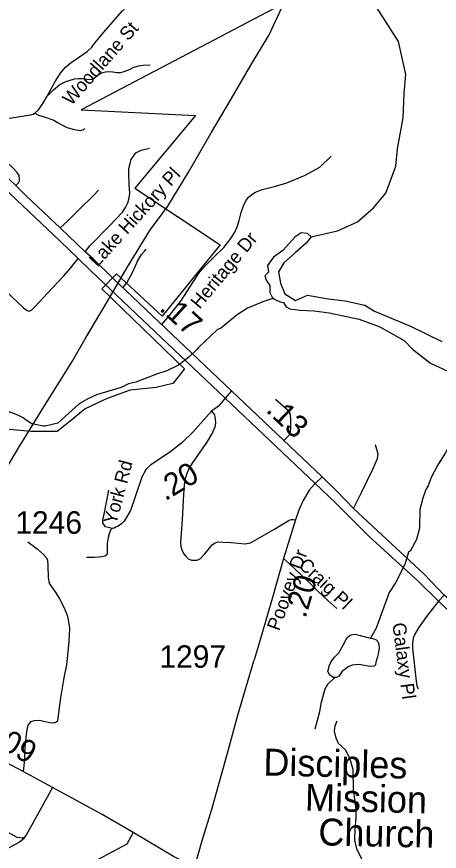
# Model space of a CAD drawing. Extents: x 1159738 to 1321356, y 736314 to 882035.
# Drawn here: x 1283208 to 1285565, y 749048 to 753698 of the extents above; entities that cross this region are included whole.
import ezdxf

# ---------------------------------------------------------------- set-up
doc = ezdxf.new("R2010")
doc.units = 0
for name, color, linetype in [('Exist Boundary Political City Limit New', 7, 'Continuous'), ('Exist Cultural Church Label', 7, 'Continuous'), ('Exist Hydrographic Creek Double Shore', 7, 'Continuous'), ('Exist Hydrographic Creek Single Shore', 7, 'Continuous'), ('Exist Hydrographic Misc Water Feature', 7, 'Continuous'), ('Exist Road Non-System Type 51', 7, 'Continuous'), ('Exist Road Non-System Type 51 Label', 7, 'Continuous'), ('Exist Road Primary US Attributed', 7, 'Continuous'), ('Exist Road Primary US Divided Attributed', 7, 'Continuous'), ('Exist Road Primary US Mileage Hundredths English Label', 7, 'Continuous'), ('Exist Road Secondary Mileage Hundredths English Label', 7, 'Continuous'), ('Exist Road Secondary Type 51 Attributed', 7, 'Continuous'), ('Exist Road Secondary Type 51 Label', 7, 'Continuous'), ('Exist Road Secondary Type 51 Number Label', 7, 'Continuous'), ('Exist Utilities Electrical Transmission Line', 7, 'Continuous'), ('Map Preparation Boundary City Limit Buffer Line', 7, 'Continuous')]:
    doc.layers.add(name, color=color, linetype=linetype)

msp = doc.modelspace()

# ---------------------------------------------------------------- linework, layer by layer
at = {"layer": 'Exist Boundary Political City Limit New'}
msp.add_lwpolyline([(1285086.5, 753976.7), (1283568.2, 753178.6), (1284205.4, 753147.8), (1283867.6, 752743), (1284343.3, 752426.5), (1284218.6, 752275.2), (1284019, 752029.4), (1283765.6, 752265.6), (1283683.1, 752181.1), (1284143.7, 751735.5), (1284078.5, 751654.9), (1283986.4, 751631.8), (1283840.5, 751616.5), (1283713.8, 751570.4), (1283591, 751512.8), (1283506.5, 751443.6), (1283433.9, 751386.4), (1283288.1, 751386.4), (1283007.9, 751413.3)], dxfattribs=at)
at = {"layer": 'Exist Hydrographic Creek Double Shore'}
for points in [[(1284849.9, 752471.5), (1284829.7, 752489.5), (1284795.7, 752493.1), (1284760.7, 752470.7), (1284727.6, 752434.9), (1284691.8, 752395.5), (1284639.9, 752357.8), (1284606.8, 752311.2), (1284613, 752274.5), (1284592.4, 752254.8), (1284599.6, 752230.6), (1284621.1, 752200.1), (1284620.2, 752160.7), (1284637.2, 752128.5), (1284677.5, 752108.8), (1284696.3, 752105.2), (1284711.4, 752080.6), (1284731.1, 752069.9), (1284787.5, 752062.7), (1284868.1, 752059.1), (1284950.4, 752048.3), (1285118.8, 752013.4), (1285234.2, 751970.4), (1285368.5, 751893.4), (1285416.4, 751845.4), (1285516.7, 751767.4), (1285693, 751685)], [(1284849.9, 752471.5), (1284822.5, 752436.2), (1284761.5, 752383.1), (1284697.8, 752327.3), (1284668.6, 752276.8), (1284679.2, 752213.1), (1284703.1, 752154.6), (1284764.1, 752117.4), (1284830.5, 752146.6), (1284944.7, 752125.4), (1285040.2, 752114.8), (1285149.1, 752090.8), (1285204.8, 752056.3), (1285403.9, 751974), (1285579.1, 751888.9)]]:
    msp.add_lwpolyline(points, dxfattribs=at)
at = {"layer": 'Exist Hydrographic Creek Single Shore'}
msp.add_lwpolyline([(1284849.9, 752471.5), (1284997.7, 752504.4), (1285108.6, 752555.7), (1285198.9, 752633.8), (1285266.6, 752713.9), (1285322.8, 752865.6), (1285332.3, 752962.4), (1285363.1, 753135), (1285369.3, 753272.6), (1285379, 753376.3), (1285336.8, 753559), (1285282.7, 753647), (1285218.8, 753745.6), (1285174, 753868.3)], dxfattribs=at)
at = {"layer": 'Exist Hydrographic Misc Water Feature'}
for points in [[(1284643.1, 752129.4), (1284580.8, 752109.2), (1284496.5, 752073.3), (1284437.4, 752037.3), (1284344.5, 751960), (1284328.3, 751954.4), (1284221.6, 751855.5), (1284215.4, 751845.7), (1284168.1, 751801.1), (1284110.9, 751756.7), (1284045.9, 751724.6), (1283989, 751706.9), (1283872.1, 751661.6), (1283831.9, 751652.7), (1283791.3, 751631.9), (1283654.1, 751591.9), (1283605.5, 751569.3), (1283556.7, 751540.6), (1283437.7, 751434.1), (1283367.5, 751416.6), (1283357.2, 751416.4), (1283293.5, 751430.2), (1283262.1, 751449.1), (1283244.5, 751463.6), (1283214.9, 751478.5), (1283151.6, 751502.2)], [(1285940.2, 751598.4), (1285871.8, 751488.3), (1285831.4, 751473.4), (1285750.3, 751433.8), (1285684.9, 751383.7), (1285656.1, 751354.5), (1285629.1, 751321.3), (1285598.5, 751266.7), (1285555.7, 751197.4), (1285517.6, 751126.5), (1285502.5, 751085), (1285490, 751063.3), (1285472.6, 751015.8), (1285456.8, 750952.3), (1285454, 750848.4), (1285438.2, 750784.9), (1285403.5, 750721), (1285394.2, 750714.1), (1285372.4, 750646.8), (1285321.5, 750544.3), (1285285.9, 750489.3), (1285212.4, 750291.5), (1285181.8, 750236.2)], [(1284982.7, 750016.3), (1284973.4, 750017), (1284953.2, 750030.5), (1284944.2, 750052.6), (1284948.6, 750067.6), (1284951.1, 750080.5), (1284960.4, 750100.9), (1284980.4, 750130.5), (1285004.2, 750153.9), (1285030.8, 750200.5), (1285050.8, 750239.7), (1285062, 750248.3), (1285073.2, 750254.9), (1285095.9, 750257.7), (1285123.7, 750250.2), (1285166.7, 750239.5), (1285181.8, 750236.2)], [(1285181.8, 750236.2), (1285195.3, 750233.3), (1285213.7, 750226), (1285221.7, 750216.8), (1285228.1, 750202.3), (1285230.4, 750181.7), (1285225.7, 750157.2), (1285220.9, 750131.2), (1285211.3, 750102.7), (1285209.6, 750087.7), (1285202.5, 750079.6), (1285179.2, 750078.2), (1285146.4, 750083.8), (1285119.1, 750088.6), (1285097.2, 750087.8), (1285079.3, 750084.8), (1285061.3, 750077), (1285041.8, 750065.2), (1285022.1, 750047.2), (1285004.5, 750024.4), (1284991.9, 750015.8), (1284982.7, 750016.3)], [(1284982.7, 750016.3), (1284941.7, 749977.3), (1284927, 749951.7), (1284904.7, 749872.4), (1284897.5, 749824.6), (1284870.8, 749729.4)]]:
    msp.add_lwpolyline(points, dxfattribs=at)
at = {"layer": 'Exist Road Non-System Type 51'}
for points in [[(1283309, 753159.6), (1283331.5, 753180.2), (1283354.8, 753214.5), (1283378.8, 753255.7), (1283423.4, 753337.6), (1283453.6, 753382.3), (1283479.6, 753414.5), (1283514.6, 753444), (1283540, 753460.5), (1283600.9, 753503.6), (1283627.7, 753528.3), (1283648.9, 753555), (1283705.2, 753623.7), (1283798.3, 753729.6), (1283853.1, 753790.7), (1283868.2, 753814.7), (1283879.2, 753838.7), (1283884, 753849)], [(1283378.8, 753255.7), (1283414.3, 753291), (1283448.6, 753320.5), (1283478.1, 753334.9), (1283501.4, 753343.1), (1283530.2, 753350.7), (1283550.8, 753353.4), (1283573.4, 753354.1), (1283591.2, 753350.7), (1283609.1, 753347.9), (1283628.9, 753349.3), (1283647.5, 753361.7), (1283663.2, 753374.7), (1283681.1, 753385.7), (1283703, 753391.2), (1283722.9, 753391.8), (1283745.5, 753390.5), (1283766.1, 753386.4), (1283788.1, 753387.7), (1283807.9, 753391.8), (1283836.7, 753403.5), (1283857.3, 753413.8), (1283887.5, 753424.8), (1283912.9, 753428.2), (1283953.3, 753429.6)], [(1283203.3, 752756.5), (1283218, 752772.9), (1283223.5, 752783.9), (1283224.8, 752795.6), (1283222.1, 752813.4), (1283210.4, 752829.2), (1283184.4, 752858), (1283161.7, 752880), (1283148, 752900.6), (1283134.3, 752923.2), (1283124.7, 752948.6), (1283111, 753005.6), (1283098, 753088.9), (1283097.3, 753097.8), (1283100.8, 753109.5), (1283115.2, 753119.8), (1283143.3, 753130.1), (1283181, 753134.2), (1283252.3, 753144.5), (1283288, 753151.3), (1283300, 753155.5), (1283309, 753159.6)], [(1283309, 753159.6), (1283330.2, 753150), (1283362.5, 753140.4), (1283415.3, 753120.5), (1283436.5, 753108.1), (1283488, 753081.3), (1283531.2, 753069.7), (1283564.1, 753064.2), (1283577.8, 753067.6), (1283590.8, 753075.2)], [(1283590.4, 752388.5), (1283615.8, 752422.1), (1283726.9, 752532.6), (1283798.2, 752609.5), (1283816.1, 752634.2), (1283828.4, 752661), (1283835.3, 752687.7), (1283838.6, 752714.2), (1283835.9, 752762.9), (1283833.1, 752821.9), (1283833.8, 752845.9), (1283835.9, 752859.7), (1283840.7, 752879.6), (1283847.5, 752901.5), (1283863.3, 752926.6), (1283872.9, 752939), (1283888, 752947.2), (1283903.1, 752954.1), (1283949.7, 752965.8)], [(1284018, 751982.9), (1284060.5, 752032.3), (1284127, 752118.1), (1284191.5, 752217), (1284229.9, 752276), (1284264.7, 752314.7), (1284309.3, 752359.3), (1284363.5, 752412.2), (1284403.3, 752462.3), (1284424.5, 752497.3), (1284438.8, 752527.8), (1284449.1, 752562.1), (1284460.8, 752607.4), (1284475.9, 752650), (1284487.5, 752673.3), (1284499.9, 752691.2), (1284519.1, 752707.6), (1284539.5, 752720.4), (1284577.2, 752734.1), (1284645.8, 752751.9), (1284715.8, 752771.9), (1284813.2, 752813.7), (1284898.9, 752859), (1284961.6, 752920.4)], [(1283450.2, 752521.5), (1283494.8, 752562.7), (1283554.5, 752621), (1283638.1, 752704.1), (1283664.2, 752731.5)], [(1282910.3, 752650.6), (1282902.1, 752630), (1282893.9, 752601.1), (1282892.5, 752573.7), (1282893.2, 752535.3), (1282900.7, 752485.8), (1282914.4, 752442.6), (1282933.5, 752408.8), (1282961, 752362.8), (1283002.1, 752312.7), (1283100.9, 752215.2), (1283181.8, 752137), (1283246.7, 752076.2), (1283266.6, 752060.5), (1283277.6, 752057.7), (1283291.3, 752063.2), (1283308.5, 752079), (1283381.8, 752159.3), (1283471.7, 752253.3), (1283507.9, 752296.3), (1283543.5, 752341.6), (1283551.7, 752350.5)], [(1283802.2, 752188.4), (1283822.1, 752215.9), (1283854.3, 752273.5), (1283877.7, 752327), (1283881.8, 752335.3), (1283905.1, 752372.3), (1283920.9, 752390.9), (1283929.8, 752401.9)], [(1284651.8, 751566.7), (1284727.2, 751499.5), (1284733.4, 751480.3), (1284735.4, 751456.3), (1284734.8, 751409.6), (1284732.7, 751385.6), (1284727.2, 751366.3), (1284719, 751356.7), (1284697.7, 751336.8)], [(1284295.7, 751499.5), (1284312.1, 751479.6), (1284316.2, 751458.3), (1284316.9, 751434.9), (1284312.8, 751410.2), (1284302.5, 751384.2), (1284268.9, 751327.9), (1284232.6, 751277.8), (1284186.7, 751211.2), (1284173, 751187.2), (1284156.5, 751153.5), (1284148.9, 751122.7), (1284142.1, 751087.7), (1284138, 751036.9), (1284130.4, 750895.5), (1284122.2, 750770.3), (1284124.3, 750746.3), (1284129.8, 750727.7), (1284138, 750707.8), (1284149.7, 750694.1), (1284164.7, 750677.6), (1284182.6, 750670.1), (1284214.1, 750670.1), (1284232.6, 750679), (1284257.3, 750705.8), (1284299.8, 750756.6), (1284315.6, 750766.9), (1284330.7, 750771.7), (1284358.8, 750771), (1284404.8, 750768.2), (1284482.3, 750760.7), (1284512.4, 750766.9), (1284641.7, 750841), (1284728.1, 750892.4), (1284740.4, 750895.9), (1284754.8, 750895.9), (1284763.8, 750895.2)], [(1285087.3, 750957.2), (1285131.5, 751046.5), (1285193.9, 751176.2), (1285219.9, 751236.6), (1285224.7, 751261.3), (1285210.3, 751313.1)], [(1283740.1, 750847.2), (1283718.1, 750851.4), (1283704.2, 750856.2), (1283695.6, 750867.5), (1283689.1, 750878.8), (1283688.6, 750893.3), (1283696.1, 750926.7), (1283722.4, 751059.2)], [(1283740.1, 750847.2), (1283731, 750837.5), (1283723.4, 750817.1), (1283718.6, 750796.1), (1283713.2, 750762.8), (1283713.2, 750707.4), (1283710, 750698.7), (1283699.3, 750692.2), (1283682.6, 750689), (1283641.8, 750685.3), (1283598.3, 750685.3)], [(1283271, 750773.1), (1283322.1, 750733.4), (1283355.4, 750704.3), (1283374.5, 750683), (1283380.2, 750670.2), (1283382.3, 750637.6), (1283383.7, 750573.8), (1283388, 750551.8), (1283392.2, 750537.6), (1283426.2, 750487.3), (1283446.7, 750454.3), (1283471.5, 750408.9), (1283489.2, 750363.5), (1283496.3, 750337.3), (1283503.4, 750291.9), (1283498.5, 750215.3), (1283485.7, 750086.6), (1283471.5, 750014.2)], [(1284696.3, 750680), (1284727.1, 750651.9), (1284832.7, 750553.1), (1284885.6, 750499.5), (1284944.5, 750446), (1284994.5, 750401.7)], [(1285560.4, 750441), (1285593.1, 750475.1)], [(1285560.4, 750441), (1285493.2, 750356.6), (1285448.6, 750293.4), (1285428.1, 750257.7), (1285419.1, 750235.8), (1285415, 750206.9), (1285415.7, 750179.5), (1285428.8, 750062.7), (1285435.7, 749996.1), (1285439.1, 749970.7), (1285448, 749953.1)], [(1284201.2, 748963.6), (1284242.9, 749108), (1284297.5, 749282.5), (1284384.9, 749594), (1284441.6, 749805.9), (1284533.3, 750114.8)], [(1283471.5, 750014.2), (1283452.2, 749902.2), (1283444.3, 749834.8), (1283436.6, 749773.1), (1283428.1, 749767.2), (1283415, 749762), (1283392.8, 749764.6), (1283334.6, 749776.4), (1283305.2, 749775.7), (1283286.2, 749768.5), (1283269.9, 749750.8), (1283264, 749716.2), (1283254.2, 749631.2), (1283250.3, 749542.8), (1283243.9, 749492.2)], [(1285160.8, 748714.9), (1285162.9, 748759.5), (1285171.4, 748866.5), (1285170.3, 748901.8), (1285158.6, 748943.6), (1285138.3, 748992.8), (1285105.1, 749062.3), (1285094.4, 749110), (1285096.6, 749172.1), (1285101.9, 749235.2), (1285100.8, 749284.5), (1285085.9, 749390.4), (1285084.8, 749503.1), (1285066.6, 749567.3), (1285042, 749613.3), (1285002.5, 749648.6), (1284989.6, 749677.5), (1284981.1, 749718.2), (1284985.4, 749747), (1284995, 749775.9)], [(1283858.9, 749153.3), (1283821.9, 749088.3), (1283771, 749060.6), (1283546.9, 748940.4)], [(1283249.8, 749125.8), (1283249.3, 749119), (1283224.4, 749099.8), (1283180.3, 749074.4), (1283139.9, 749052.5), (1283121.7, 749033.8)]]:
    msp.add_lwpolyline(points, dxfattribs=at)
at = {"layer": 'Exist Road Primary US Attributed'}
for points in [[(1283407.4, 749404.1), (1283306.3, 749458.5), (1283243.9, 749492.2), (1283073.5, 749582.2), (1282976.8, 749635.9)], [(1286675.2, 748116.7), (1286461.5, 748240.3), (1286275.2, 748348.8), (1286158, 748417), (1286032.3, 748489.6), (1285885, 748573.2), (1285741.8, 748641.3), (1285612.7, 748681.1), (1285461.2, 748705.6), (1285417.3, 748710.2), (1285160.8, 748714.9), (1284962.1, 748721.8), (1284717.2, 748738), (1284590.1, 748765.7), (1284498.9, 748808.8), (1284339.5, 748887.4), (1284189.3, 748966), (1284083, 749019.2), (1283858.9, 749153.3), (1283685.6, 749252.7), (1283497.3, 749354.4), (1283407.4, 749404.1)]]:
    msp.add_lwpolyline(points, dxfattribs=at)
at = {"layer": 'Exist Road Primary US Divided Attributed'}
msp.add_line((1284370.9, 751572.6), (1284872.9, 751097.8), dxfattribs=at)
for points in [[(1281205.3, 754875), (1281282.7, 754750.9), (1281327.3, 754673.8), (1281422.8, 754516.8), (1281495.9, 754411.3), (1281539, 754348.9), (1281607.8, 754256.1), (1281659.7, 754192.1), (1281733.9, 754102), (1281817.1, 754010.1), (1281889.7, 753933.7), (1281977.6, 753846.5), (1282175.6, 753654.8), (1282321.8, 753516.3), (1282602, 753249.9), (1282794.5, 753067.1), (1282993.2, 752875.7), (1283115.9, 752762.2), (1283169.4, 752712.1), (1283311, 752579.4), (1283449.2, 752449), (1283551.7, 752350.5), (1283622.4, 752282.2), (1284370.9, 751572.6)], [(1284406.3, 751613.3), (1283745.3, 752241.8), (1283636.2, 752347), (1283590.4, 752388.5), (1283450.2, 752521.5), (1283263.2, 752698.3), (1283203.3, 752756.5), (1282971, 752973.8), (1282755.9, 753180.7), (1282403.6, 753512.5), (1282105.3, 753798.8), (1281961.9, 753936.1), (1281907.4, 753991.9), (1281804.9, 754105.5), (1281722.9, 754199.3), (1281650.6, 754291.4)], [(1284912.1, 751134.3), (1284406.3, 751613.3)], [(1284872.9, 751097.8), (1284986.3, 750989.7), (1285174.8, 750801.2), (1285446.5, 750553.2), (1285560.4, 750441), (1285596.1, 750408.8), (1285753.3, 750258.2), (1285967, 750055.5), (1286666.3, 749398.8), (1287841.8, 748278.8), (1288179.5, 747958.8), (1288566, 747590.6), (1288742, 747424.7), (1288842.6, 747327.9), (1289075.6, 747102.7), (1289184.2, 746990.5), (1289284.9, 746874.5)], [(1289566.8, 746622.3), (1289339.6, 746898.3), (1289190.4, 747065.5), (1288874.1, 747374), (1288770.3, 747471.8), (1288618.2, 747616.8), (1288206.3, 748007), (1287893.4, 748301.5), (1287879.6, 748317.4), (1286883.7, 749263.7), (1286696.8, 749439.3), (1286597.1, 749535), (1286435.2, 749688.5), (1286334.8, 749781.3), (1285667, 750411.7), (1285593.1, 750475.1), (1285480.4, 750591.9), (1285087.3, 750957.2), (1284989.7, 751058.2), (1284912.1, 751134.3)]]:
    msp.add_lwpolyline(points, dxfattribs=at)
at = {"layer": 'Exist Road Secondary Type 51 Attributed'}
for points in [[(1284406.3, 751613.3), (1284370.9, 751572.6)], [(1284370.9, 751572.6), (1284333.8, 751528), (1284295.7, 751499.5), (1284191.4, 751383.4), (1284129.3, 751323.9), (1284068, 751275), (1283955.3, 751199.9), (1283930.1, 751176.2), (1283907, 751133.3), (1283871.1, 751027.7), (1283843.7, 750946.5), (1283807.8, 750888.1), (1283793.8, 750873), (1283774.5, 750860.1), (1283761.1, 750853.1), (1283751.4, 750848.3), (1283740.1, 750847.2)], [(1284872.9, 751097.8), (1284839.8, 751060.8), (1284806.2, 751002.3), (1284782.5, 750948.8), (1284763.8, 750895.2), (1284696.3, 750680), (1284635.3, 750462.7), (1284606.2, 750359.2), (1284556.5, 750194.4), (1284533.3, 750114.8)], [(1284912.1, 751134.3), (1284872.9, 751097.8)], [(1283407.4, 749404.1), (1283262.2, 749137.4), (1283249.8, 749125.8), (1283239.4, 749121.8), (1283226.4, 749122.3), (1283211.4, 749125.9), (1283126.8, 749171.6), (1283029.8, 749224.2)]]:
    msp.add_lwpolyline(points, dxfattribs=at)
at = {"layer": 'Exist Utilities Electrical Transmission Line'}
msp.add_lwpolyline([(1283104.8, 751106.6), (1283216.9, 751291.9), (1283344.8, 751499.6), (1283518.6, 751776.8), (1283589.5, 751903.5), (1283724.5, 752127.1), (1283824.2, 752299.6), (1283950.3, 752506.7), (1284051.1, 752642.4), (1284165.7, 752831.5), (1284292.6, 753050.6), (1284405.8, 753242.1), (1284514.5, 753428.5), (1284616.8, 753596.1), (1284688.5, 753751.9)], dxfattribs=at)
at = {"layer": 'Map Preparation Boundary City Limit Buffer Line'}
msp.add_lwpolyline([(1285086.5, 753976.7), (1283568.2, 753178.6), (1284205.4, 753147.8), (1283867.6, 752743), (1284343.3, 752426.5), (1284218.6, 752275.2), (1284019, 752029.4), (1283765.6, 752265.6), (1283683.1, 752181.1), (1284143.7, 751735.5), (1284078.5, 751654.9), (1283986.4, 751631.8), (1283840.5, 751616.5), (1283713.8, 751570.4), (1283591, 751512.8), (1283506.5, 751443.6), (1283433.9, 751386.4), (1283288.1, 751386.4), (1283007.9, 751413.3)], dxfattribs=at)

# ---------------------------------------------------------------- texts
at = {"layer": 'Exist Cultural Church Label'}
for s, p in [('Disciples ', (1284583, 749470.6)), ('Mission', (1284815.1, 749274.5)), ('Church', (1284889.7, 749081.8))]:
    msp.add_text(s, height=150, rotation=358.7401, dxfattribs=at).set_placement(p)
at = {"layer": 'Exist Road Non-System Type 51 Label'}
for s, rotation, p in [('Woodlane St', 48.6204, (1283513.1, 753198.5)), ('Lake Hickory Pl', 47.7125, (1283659, 752299.1)), ('Heritage Dr', 50.2266, (1284228.6, 752065.3)), ('Craig Pl', 316.4863, (1284775.6, 750635.5)), ('Galaxy Pl', 277.6204, (1285303, 750317))]:
    msp.add_text(s, height=75, rotation=rotation, dxfattribs=at).set_placement(p)
at = {"layer": 'Exist Road Primary US Mileage Hundredths English Label'}
for s, rotation, p in [('.17', 317.5453, (1283999.1, 752066.9)), ('.13', 316.3521, (1284593.6, 751501.1)), ('.09', 330.6619, (1283070.7, 749645.2))]:
    msp.add_text(s, height=125, rotation=rotation, dxfattribs=at).set_placement(p)
at = {"layer": 'Exist Road Secondary Mileage Hundredths English Label'}
for rotation, p in [(31.282, (1284036.9, 750997.2)), (73.2797, (1284818.9, 750342.1))]:
    msp.add_text('.20', height=125, rotation=rotation, dxfattribs=at).set_placement(p)
at = {"layer": 'Exist Road Secondary Type 51 Label'}
for s, rotation, p in [('York Rd', 75.2, (1283763.3, 750864.9)), ('Poovey Dr', 70.0876, (1284672.1, 750271.9))]:
    msp.add_text(s, height=75, rotation=rotation, dxfattribs=at).set_placement(p)
at = {"layer": 'Exist Road Secondary Type 51 Number Label'}
for s, p in [('1246', (1283200.8, 750817.4)), ('1297', (1284004, 750070.7))]:
    msp.add_text(s, height=125, dxfattribs=at).set_placement(p)

doc.saveas('drawing.dxf')
